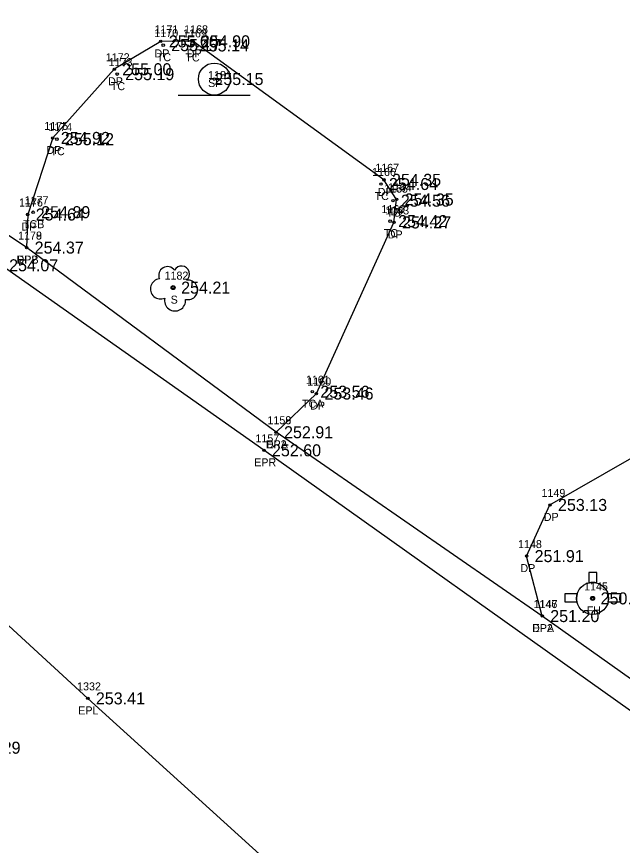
# Model space of a CAD drawing. Extents: x 1961231 to 1962574, y 799865 to 801120.
# Drawn here: x 1962025.9 to 1962101.5, y 800468.6 to 800572.1 of the extents above; entities that cross this region are included whole.
import ezdxf

# ---------------------------------------------------------------- set-up
doc = ezdxf.new("R2010")
doc.units = 0
for name, color, linetype in [('RD_EX_BldgApp', 7, 'Continuous'), ('RD_EX_BldgApp_txCode', 7, 'Continuous'), ('RD_EX_Conc_txCode', 7, 'Continuous'), ('RD_EX_Driveway', 7, 'Continuous'), ('RD_EX_Driveway_txCode', 7, 'Continuous'), ('RD_EX_Road', 7, 'Continuous'), ('RD_EX_Road_txCode', 7, 'Continuous'), ('RD_EX_TX_BldgApp_ELEV', 7, 'Continuous'), ('RD_EX_TX_Conc_ELEV', 7, 'Continuous'), ('RD_EX_TX_Driveway_ELEV', 7, 'Continuous'), ('RD_EX_TX_Road_ELEV', 7, 'Continuous'), ('RD_EX_TX_UT_ELEV', 7, 'Continuous'), ('RD_EX_TX_VEG_ELEV', 7, 'Continuous'), ('RD_EX_UT', 7, 'Continuous'), ('RD_EX_UT_txCode', 7, 'Continuous'), ('RD_EX_VEG', 7, 'Continuous'), ('RD_EX_VEG_txCode', 7, 'Continuous'), ('RD_SMD_Locator', 7, 'Continuous')]:
    doc.layers.add(name, color=color, linetype=linetype)

msp = doc.modelspace()

# ---------------------------------------------------------------- linework, layer by layer
at = {"layer": 'RD_EX_BldgApp'}
msp.add_line((1962046.06, 800562.29), (1962055.06, 800562.29), dxfattribs=at)
msp.add_circle((1962050.58, 800564.31), 2, dxfattribs=at)
at = {"layer": 'RD_EX_Driveway'}
for points in [[(1962058.28, 800520.2), (1962063.32, 800525.03), (1962073.01, 800546.4), (1962073.33, 800549.27), (1962071.76, 800551.72), (1962047.9, 800569.02), (1962043.89, 800569.01), (1962038.08, 800565.53), (1962030.4, 800556.95), (1962027.27, 800547.39), (1962027.14, 800543.26)], [(1962091.52, 800497.24), (1962089.57, 800504.73), (1962092.49, 800511.12), (1962102.73, 800516.99), (1962107.6, 800525.32), (1962111.65, 800535.64)]]:
    msp.add_lwpolyline(points, dxfattribs=at)
at = {"layer": 'RD_EX_Road'}
for points in [[(1962276.74, 800366.53), (1962275.76, 800367.28), (1962226.46, 800400.66), (1962183.05, 800429.73), (1962145.98, 800455.38), (1962104.4, 800484.06), (1962056.77, 800517.94), (1962023.95, 800541.05), (1961991.87, 800563.56), (1961983.89, 800569.94), (1961938.77, 800603.67), (1961913.43, 800623.83), (1961897.73, 800636.17), (1961851.62, 800671.61), (1961815.86, 800699.48), (1961795.77, 800715.49), (1961771.88, 800733.73), (1961750.77, 800750.96), (1961735.63, 800762.82), (1961702.92, 800788.52)], [(1962241.79, 800315.68), (1962238.35, 800317.6), (1962189.92, 800352.69), (1962151.64, 800383.49), (1962113.78, 800416.39), (1962074.11, 800451.29), (1962034.78, 800486.96), (1962017.07, 800503.17), (1961999.46, 800519.25), (1961962.48, 800552.12), (1961937.08, 800573.11), (1961923.19, 800584.9), (1961883.07, 800617.43), (1961838.29, 800653.43), (1961801.42, 800682.57), (1961728.41, 800740.86), (1961722.95, 800745.11), (1961689.13, 800771.93)], [(1962275.76, 800367.28), (1962274.03, 800371.18), (1962275.17, 800373.82), (1962239.93, 800394.94), (1962227.76, 800403.12), (1962207.73, 800416.44), (1962184.45, 800431.68), (1962152.89, 800453.77), (1962107.43, 800485.96), (1962091.52, 800497.24), (1962058.28, 800520.2), (1962027.14, 800543.26), (1961995.14, 800564.69), (1961983.89, 800569.94)]]:
    msp.add_lwpolyline(points, dxfattribs=at)
at = {"layer": 'RD_EX_UT'}
for p, q in [((1962097.35, 800502.67), (1962097.35, 800501.4)), ((1962098.35, 800502.67), (1962097.35, 800502.67)), ((1962098.35, 800501.38), (1962098.35, 800502.67)), ((1962095.89, 800500.03), (1962094.34, 800500.03)), ((1962094.34, 800500.03), (1962094.34, 800499.03)), ((1962101.34, 800500.03), (1962099.73, 800500.03)), ((1962101.34, 800499.03), (1962101.34, 800500.03)), ((1962094.34, 800499.03), (1962095.86, 800499.03)), ((1962099.76, 800499.03), (1962101.34, 800499.03))]:
    msp.add_line(p, q, dxfattribs=at)
for radius in [2, 0.25]:
    msp.add_circle((1962097.81, 800499.45), radius, dxfattribs=at)
for start, end in [(74.2455, 103.2128), (163.3387, 192.315), (347.685, 16.6613)]:
    msp.add_arc((1962097.81, 800499.45), 2, start, end, dxfattribs=at)
at = {"layer": 'RD_EX_VEG'}
msp.add_circle((1962045.43, 800538.26), 0.25, dxfattribs=at)
for centre, radius, start, end in [((1962044.71, 800539.8), 1.08, 34.9763, 204.756), ((1962046.47, 800539.96), 0.995, 308.7626, 152.0467), ((1962043.86, 800538.1), 1.26, 96.4518, 294.734), ((1962047.27, 800537.98), 1.22, 256.5667, 98.1046), ((1962045.67, 800536.66), 1.32, 166.8827, 5.7589)]:
    msp.add_arc(centre, radius, start, end, dxfattribs=at)
at = {"layer": 'RD_SMD_Locator'}
for centre in [(1962043.89, 800569.01), (1962044.19, 800568.54), (1962047.76, 800568.51), (1962047.9, 800569.02), (1962038.08, 800565.53), (1962038.44, 800564.92), (1962050.58, 800564.31), (1962030.4, 800556.95), (1962030.91, 800556.8), (1962071.38, 800551.2), (1962071.76, 800551.72), (1962072.87, 800549.12), (1962073.33, 800549.27), (1962027.95, 800547.68), (1962027.27, 800547.39), (1962072.53, 800546.56), (1962073.01, 800546.4), (1962027.14, 800543.26), (1962027.14, 800543.26), (1962045.43, 800538.26), (1962062.81, 800525.26), (1962063.32, 800525.03), (1962058.28, 800520.2), (1962058.28, 800520.2), (1962056.77, 800517.94), (1962092.49, 800511.12), (1962089.57, 800504.73), (1962097.81, 800499.45), (1962091.52, 800497.24), (1962091.52, 800497.24), (1962034.78, 800486.96)]:
    msp.add_circle(centre, 0.15, dxfattribs=at)

# ---------------------------------------------------------------- texts
at = {"layer": 'RD_EX_BldgApp_txCode'}
for s, p in [('1181', (1962049.8, 800564.31)), ('SP', (1962049.8, 800563.31))]:
    msp.add_text(s, height=1, dxfattribs=at).set_placement(p)
at = {"layer": 'RD_EX_Conc_txCode'}
for s, p in [('1170', (1962043.08, 800569.54)), ('1169', (1962046.67, 800569.51)), ('TC', (1962043.39, 800566.54)), ('TC', (1962046.96, 800566.51)), ('1173', (1962037.38, 800565.92)), ('TC', (1962037.65, 800562.92)), ('1174', (1962029.84, 800557.8)), ('TC', (1962030.11, 800554.8)), ('1166', (1962070.27, 800552.2)), ('1165', (1962071.78, 800550.12)), ('TC', (1962070.59, 800549.2)), ('1177', (1962026.89, 800548.68)), ('1162', (1962071.44, 800547.56)), ('TC', (1962072.07, 800547.12)), ('TCB', (1962026.68, 800545.68)), ('TC', (1962071.73, 800544.56)), ('1161', (1962062.01, 800526.26)), ('TCA', (1962061.53, 800523.26))]:
    msp.add_text(s, height=1, dxfattribs=at).set_placement(p)
at = {"layer": 'RD_EX_Driveway_txCode'}
for s, p in [('1171', (1962043.11, 800570.01)), ('1168', (1962046.81, 800570.02)), ('1172', (1962037.02, 800566.53)), ('DP', (1962043.11, 800567.01)), ('DP', (1962047.12, 800567.02)), ('DP', (1962037.3, 800563.53)), ('1175', (1962029.34, 800557.95)), ('DP', (1962029.62, 800554.95)), ('1167', (1962070.67, 800552.72)), ('1164', (1962072.25, 800550.27)), ('DP', (1962070.98, 800549.72)), ('1176', (1962026.19, 800548.39)), ('1163', (1962071.92, 800547.4)), ('DP', (1962072.55, 800547.27)), ('DP', (1962026.5, 800545.39)), ('1178', (1962026.07, 800544.26)), ('DP', (1962072.23, 800544.4)), ('DPB', (1962025.88, 800541.26)), ('1160', (1962062.19, 800526.03)), ('DP', (1962062.54, 800523.03)), ('1159', (1962057.21, 800521.2)), ('DPA', (1962057.01, 800518.2)), ('1149', (1962091.43, 800512.12)), ('DP', (1962091.71, 800509.12)), ('1148', (1962088.5, 800505.73)), ('DP', (1962088.79, 800502.73)), ('1147', (1962090.46, 800498.24)), ('DPA', (1962090.25, 800495.24))]:
    msp.add_text(s, height=1, dxfattribs=at).set_placement(p)
at = {"layer": 'RD_EX_Road_txCode'}
for s, p in [('1179', (1962026.07, 800544.26)), ('EP2', (1962025.93, 800541.26)), ('1158', (1962057.21, 800521.2)), ('1157', (1962055.71, 800518.94)), ('EP2', (1962057.07, 800518.2)), ('EPR', (1962055.55, 800515.94)), ('1146', (1962090.43, 800498.24)), ('EP2', (1962090.32, 800495.24)), ('1332', (1962033.44, 800487.96)), ('EPL', (1962033.58, 800484.96))]:
    msp.add_text(s, height=1, dxfattribs=at).set_placement(p)
at = {"layer": 'RD_EX_TX_BldgApp_ELEV'}
msp.add_text('255.15', height=1.5, dxfattribs=at).set_placement((1962050.58, 800563.56))
at = {"layer": 'RD_EX_TX_Conc_ELEV'}
for s, p in [('255.17', (1962045.19, 800567.79)), ('255.14', (1962048.76, 800567.76)), ('255.19', (1962039.44, 800564.17)), ('255.12', (1962031.91, 800556.05)), ('254.64', (1962072.38, 800550.45)), ('254.56', (1962073.87, 800548.37)), ('254.89', (1962028.95, 800546.93)), ('254.42', (1962073.53, 800545.81)), ('253.56', (1962063.81, 800524.51))]:
    msp.add_text(s, height=1.5, dxfattribs=at).set_placement(p)
at = {"layer": 'RD_EX_TX_Driveway_ELEV'}
for s, p in [('255.00', (1962044.89, 800568.26)), ('254.90', (1962048.9, 800568.27)), ('255.00', (1962039.08, 800564.78)), ('254.92', (1962031.4, 800556.2)), ('254.35', (1962072.76, 800550.97)), ('254.35', (1962074.33, 800548.52)), ('254.64', (1962028.27, 800546.64)), ('254.27', (1962074.01, 800545.65)), ('254.37', (1962028.14, 800542.51)), ('253.46', (1962064.32, 800524.28)), ('252.91', (1962059.28, 800519.45)), ('253.13', (1962093.49, 800510.37)), ('251.91', (1962090.57, 800503.98)), ('251.20', (1962092.52, 800496.49))]:
    msp.add_text(s, height=1.5, dxfattribs=at).set_placement(p)
at = {"layer": 'RD_EX_TX_Road_ELEV'}
for s, p in [('254.37', (1962028.14, 800542.51)), ('254.07', (1962024.95, 800540.3)), ('252.91', (1962059.28, 800519.45)), ('252.60', (1962057.77, 800517.19)), ('251.20', (1962092.52, 800496.49)), ('253.41', (1962035.78, 800486.21)), ('254.29', (1962020.24, 800480.05))]:
    msp.add_text(s, height=1.5, dxfattribs=at).set_placement(p)
at = {"layer": 'RD_EX_TX_UT_ELEV'}
msp.add_text('250.65', height=1.5, dxfattribs=at).set_placement((1962098.81, 800498.7))
at = {"layer": 'RD_EX_TX_VEG_ELEV'}
msp.add_text('254.21', height=1.5, dxfattribs=at).set_placement((1962046.43, 800537.51))
at = {"layer": 'RD_EX_UT_txCode'}
for s, p in [('1145', (1962096.75, 800500.45)), ('FH', (1962097.08, 800497.45))]:
    msp.add_text(s, height=1, dxfattribs=at).set_placement(p)
at = {"layer": 'RD_EX_VEG_txCode'}
for s, p in [('1182', (1962044.36, 800539.26)), ('S', (1962045.12, 800536.26))]:
    msp.add_text(s, height=1, dxfattribs=at).set_placement(p)

doc.saveas('drawing.dxf')
